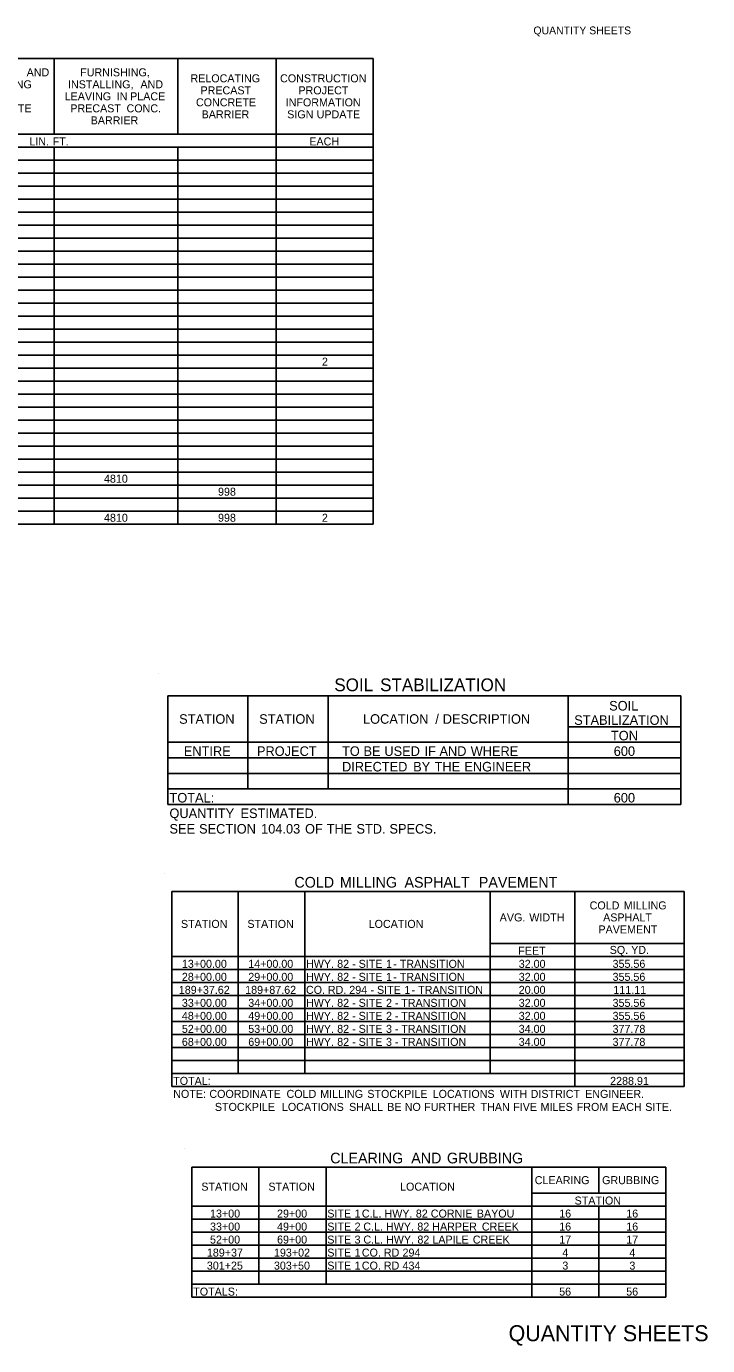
# Model space of a CAD drawing. Extents: x 977434 to 989596, y 1525697 to 1528336.
# Drawn here: x 980105 to 980615, y 1527332 to 1528321 of the extents above; entities that cross this region are included whole.
import ezdxf

# ---------------------------------------------------------------- set-up
doc = ezdxf.new("R2010")
doc.units = 0
for name, color, linetype in [('Default', 7, 'Continuous'), ('R_Border', 7, 'Continuous'), ('R_Border Prem', 7, 'Continuous')]:
    doc.layers.add(name, color=color, linetype=linetype)

msp = doc.modelspace()

# ---------------------------------------------------------------- linework, layer by layer
at = {"layer": 'Default'}
for p, q in [((979105.72, 1528296.72), (980364.94, 1528296.72)), ((980126.06, 1528240.17), (980126.06, 1528296.72)), ((980218.69, 1528240.17), (980218.69, 1528296.72)), ((980292.3, 1527947.67), (980292.3, 1528296.72)), ((980364.94, 1527947.67), (980364.94, 1528296.72)), ((980364.94, 1527947.67), (980364.94, 1528296.72)), ((979749.22, 1528240.17), (980364.94, 1528240.17)), ((980000.29, 1528240.17), (980364.94, 1528240.17)), ((979105.72, 1528230.42), (980364.94, 1528230.42)), ((979691.21, 1528230.42), (980364.94, 1528230.42)), ((980126.06, 1527947.67), (980126.06, 1528230.42)), ((980126.06, 1527947.67), (980126.06, 1528230.42)), ((980218.69, 1527947.67), (980218.69, 1528230.42)), ((980218.69, 1527947.67), (980218.69, 1528230.42)), ((979105.72, 1528220.67), (980364.94, 1528220.67)), ((979105.72, 1528210.92), (980364.94, 1528210.92)), ((979105.72, 1528201.17), (980364.94, 1528201.17)), ((979105.72, 1528191.42), (980364.94, 1528191.42)), ((979105.72, 1528181.67), (980364.94, 1528181.67)), ((979105.72, 1528171.92), (980364.94, 1528171.92)), ((979105.72, 1528162.17), (980364.94, 1528162.17)), ((979105.72, 1528152.42), (980364.94, 1528152.42)), ((979105.72, 1528142.67), (980364.94, 1528142.67)), ((979105.72, 1528132.92), (980364.94, 1528132.92)), ((979105.72, 1528123.17), (980364.94, 1528123.17)), ((979105.72, 1528113.42), (980364.94, 1528113.42)), ((979105.72, 1528103.67), (980364.94, 1528103.67)), ((979105.72, 1528093.92), (980364.94, 1528093.92)), ((979105.72, 1528084.17), (980364.94, 1528084.17)), ((979105.72, 1528074.42), (980364.94, 1528074.42)), ((979105.72, 1528064.67), (980364.94, 1528064.67)), ((979105.72, 1528054.92), (980364.94, 1528054.92)), ((979105.72, 1528045.17), (980364.94, 1528045.17)), ((979105.72, 1528035.42), (980364.94, 1528035.42)), ((979105.72, 1528025.67), (980364.94, 1528025.67)), ((979105.72, 1528015.92), (980364.94, 1528015.92)), ((979105.72, 1528006.17), (980364.94, 1528006.17)), ((979105.72, 1527996.42), (980364.94, 1527996.42)), ((979105.72, 1527986.67), (980364.94, 1527986.67)), ((980048.55, 1527986.67), (980292.3, 1527986.67)), ((980292.3, 1527986.67), (980364.94, 1527986.67)), ((979105.72, 1527976.92), (980364.94, 1527976.92)), ((980048.55, 1527976.92), (980292.3, 1527976.92)), ((980292.3, 1527976.92), (980364.94, 1527976.92)), ((979105.72, 1527967.17), (980364.94, 1527967.17)), ((979105.72, 1527957.42), (980364.94, 1527957.42)), ((979105.72, 1527947.67), (980364.94, 1527947.67)), ((980211.16, 1527819.14), (980595.38, 1527819.14)), ((980211.16, 1527737.63), (980211.16, 1527819.14)), ((980211.16, 1527737.63), (980211.16, 1527819.14)), ((980271.12, 1527749.28), (980271.12, 1527819.14)), ((980331.08, 1527749.28), (980331.08, 1527819.14)), ((980510.97, 1527737.63), (980510.97, 1527819.14)), ((980595.38, 1527737.63), (980595.38, 1527819.14)), ((980595.38, 1527737.63), (980595.38, 1527819.14)), ((980510.97, 1527795.85), (980595.38, 1527795.85)), ((980211.16, 1527784.21), (980595.38, 1527784.21)), ((980211.16, 1527784.21), (980595.38, 1527784.21)), ((980271.12, 1527749.28), (980271.12, 1527784.21)), ((980331.08, 1527749.28), (980331.08, 1527784.21)), ((980510.97, 1527749.28), (980510.97, 1527784.21)), ((980211.16, 1527772.56), (980595.38, 1527772.56)), ((980211.16, 1527760.92), (980595.38, 1527760.92)), ((980211.16, 1527749.28), (980271.12, 1527749.28)), ((980211.16, 1527749.28), (980595.38, 1527749.28)), ((980211.16, 1527737.63), (980595.38, 1527737.63)), ((980214.14, 1527672.44), (980597.8, 1527672.44)), ((980214.14, 1527526.19), (980214.14, 1527672.44)), ((980214.14, 1527526.19), (980214.14, 1527672.44)), ((980263.87, 1527535.94), (980263.87, 1527672.44)), ((980313.59, 1527535.94), (980313.59, 1527672.44)), ((980452.53, 1527535.94), (980452.53, 1527672.44)), ((980515.9, 1527526.19), (980515.9, 1527672.44)), ((980597.8, 1527526.19), (980597.8, 1527672.44)), ((980597.8, 1527526.19), (980597.8, 1527672.44)), ((980452.53, 1527633.44), (980597.8, 1527633.44)), ((980452.53, 1527535.94), (980452.53, 1527633.44)), ((980214.14, 1527623.69), (980597.8, 1527623.69)), ((980263.87, 1527535.94), (980263.87, 1527623.69)), ((980313.59, 1527535.94), (980313.59, 1527623.69)), ((980515.9, 1527535.94), (980515.9, 1527623.69)), ((980214.14, 1527613.94), (980597.8, 1527613.94)), ((980214.14, 1527604.19), (980597.8, 1527604.19)), ((980214.14, 1527594.44), (980597.8, 1527594.44)), ((980214.14, 1527584.69), (980597.8, 1527584.69)), ((980214.14, 1527574.94), (980597.8, 1527574.94)), ((980214.14, 1527565.19), (980597.8, 1527565.19)), ((980214.14, 1527555.44), (980597.8, 1527555.44)), ((980214.14, 1527545.69), (980597.8, 1527545.69)), ((980214.14, 1527535.94), (980263.87, 1527535.94)), ((980214.14, 1527535.94), (980597.8, 1527535.94)), ((980263.87, 1527535.94), (980313.59, 1527535.94)), ((980313.59, 1527535.94), (980452.53, 1527535.94)), ((980515.9, 1527535.94), (980597.8, 1527535.94)), ((980214.14, 1527526.19), (980597.8, 1527526.19)), ((980229.15, 1527465.73), (980584.05, 1527465.73)), ((980229.15, 1527368.23), (980229.15, 1527465.73)), ((980229.15, 1527368.23), (980229.15, 1527465.73)), ((980279.36, 1527377.98), (980279.36, 1527465.73)), ((980329.58, 1527377.98), (980329.58, 1527465.73)), ((980483.63, 1527368.23), (980483.63, 1527465.73)), ((980533.84, 1527446.23), (980533.84, 1527465.73)), ((980584.05, 1527368.23), (980584.05, 1527465.73)), ((980584.05, 1527446.23), (980584.05, 1527465.73)), ((980483.63, 1527446.23), (980584.05, 1527446.23)), ((980483.63, 1527377.98), (980483.63, 1527446.23)), ((980229.15, 1527436.48), (980584.05, 1527436.48)), ((980533.84, 1527368.23), (980533.84, 1527436.48)), ((980533.84, 1527368.23), (980533.84, 1527436.48)), ((980584.05, 1527377.98), (980584.05, 1527436.48)), ((980229.15, 1527426.73), (980584.05, 1527426.73)), ((980229.15, 1527416.98), (980584.05, 1527416.98)), ((980229.15, 1527407.23), (980584.05, 1527407.23)), ((980279.36, 1527377.98), (980279.36, 1527407.23)), ((980329.58, 1527377.98), (980329.58, 1527407.23)), ((980229.15, 1527397.48), (980584.05, 1527397.48)), ((980229.15, 1527387.73), (980584.05, 1527387.73)), ((980229.15, 1527377.98), (980584.05, 1527377.98)), ((980329.58, 1527377.98), (980584.05, 1527377.98)), ((980229.15, 1527368.23), (980584.05, 1527368.23))]:
    msp.add_line(p, q, dxfattribs=at)
at = {"layer": 'R_Border Prem'}
for p, q in [((980204.17, 1527835.44), (980204.17, 1527835.44)), ((980208.29, 1527686.09), (980208.29, 1527686.09)), ((980223.3, 1527479.38), (980223.3, 1527479.38))]:
    msp.add_line(p, q, dxfattribs=at)

# ---------------------------------------------------------------- texts
at = {"layer": 'Default'}
for s, height, p in [(' AND', 6, (980103.1, 1528283.44)), ('FURNISHING,', 6, (980145.43, 1528283.44)), ('INSTALLING', 6, (980062.41, 1528274.44)), ('INSTALLING,', 6, (980136.32, 1528274.44)), (' AND', 6, (980188.35, 1528274.44)), ('RELOCATING', 6, (980228.03, 1528278.94)), ('CONSTRUCTION', 6, (980295.18, 1528278.94)), ('LEAVING', 6, (980133.81, 1528265.44)), (' IN', 6, (980170.57, 1528265.44)), (' PLACE', 6, (980180.61, 1528265.44)), ('PRECAST', 6, (980235.55, 1528269.94)), ('PROJECT', 6, (980308.9, 1528269.94)), ('CONCRETE', 6, (980063.99, 1528256.44)), ('PRECAST', 6, (980138.04, 1528256.44)), (' CONC.', 6, (980177.94, 1528256.44)), ('CONCRETE', 6, (980232.18, 1528260.94)), ('INFORMATION', 6, (980299.38, 1528260.94)), ('BARRIER', 6, (980153.3, 1528247.44)), ('BARRIER', 6, (980236.41, 1528251.94)), ('SIGN', 6, (980300.51, 1528251.94)), (' UPDATE', 6, (980320.34, 1528251.94)), ('LIN.', 6, (980107.37, 1528231.62)), (' FT.', 6, (980122.63, 1528231.62)), ('EACH', 6, (980317.06, 1528231.62)), ('2', 6, (980326.51, 1528066.54)), ('4810', 6, (980163.25, 1527978.79)), ('998', 6, (980248.69, 1527969.04)), ('4810', 6, (980163.26, 1527949.54)), ('998', 6, (980248.69, 1527949.54)), ('2', 6, (980326.5, 1527949.54)), ('SOIL', 9.553, (980335.78, 1527822.51)), (' STABILIZATION', 9.5534, (980366.53, 1527822.51)), ('SOIL', 7.165, (980541.65, 1527808.03)), ('STATION', 7.165, (980219.57, 1527798.09)), ('STATION', 7.165, (980279.53, 1527798.09)), ('LOCATION', 7.165, (980357.3, 1527798.09)), (' /', 7.165, (980408.78, 1527798.09)), (' DESCRIPTION', 7.165, (980414.35, 1527798.09)), ('STABILIZATION', 7.165, (980515.48, 1527797.28)), ('TON', 7.165, (980543.01, 1527785.64)), ('ENTIRE', 7.165, (980223.05, 1527774)), ('PROJECT', 7.165, (980277.84, 1527774)), ('TO', 7.165, (980341.56, 1527774)), (' BE', 7.165, (980355.02, 1527774)), (' USED', 7.165, (980370.62, 1527774)), (' IF', 7.165, (980400.68, 1527774)), (' AND', 7.165, (980411.9, 1527774)), (' WHERE', 7.165, (980435.29, 1527774)), ('600', 7.165, (980545.07, 1527774)), ('DIRECTED', 7.165, (980341.56, 1527762.35)), (' BY', 7.165, (980392.2, 1527762.35)), (' THE', 7.165, (980408.26, 1527762.35)), (' ENGINEER', 7.165, (980430.53, 1527762.35)), ('TOTAL:', 7.165, (980212.32, 1527739.07)), ('600', 7.165, (980545.07, 1527739.07)), ('QUANTITY', 7.165, (980212.32, 1527727.42)), (' ESTIMATED.', 7.165, (980262.86, 1527727.42)), ('SEE', 7.165, (980212.32, 1527715.78)), (' SECTION', 7.165, (980231.82, 1527715.78)), (' 104.03', 7.165, (980278.29, 1527715.78)), (' OF', 7.165, (980311.22, 1527715.78)), (' THE', 7.165, (980327.44, 1527715.78)), (' STD.', 7.165, (980349.71, 1527715.78)), (' SPECS.', 7.165, (980374.43, 1527715.78)), ('COLD', 8, (980305.9, 1527675.27)), (' MILLING', 8, (980337.02, 1527675.27)), (' ASPHALT', 8, (980385.39, 1527675.27)), (' PAVEMENT', 8, (980441.06, 1527675.27)), ('COLD', 6, (980527.05, 1527658.94)), (' MILLING', 6, (980550.38, 1527658.94)), ('STATION', 6, (980220.94, 1527645.07)), ('STATION', 6, (980270.67, 1527645.07)), ('LOCATION', 6, (980361.51, 1527645.07)), ('AVG.', 6, (980459.68, 1527649.94)), (' WIDTH', 6, (980479.6, 1527649.94)), ('PAVEMENT', 6, (980533.65, 1527640.94)), ('ASPHALT', 6, (980537.14, 1527649.94)), ('FEET', 6, (980473.59, 1527624.89)), ('SQ.', 6, (980542.06, 1527625.57)), (' YD.', 6, (980555.92, 1527625.57)), ('13+00.00', 6, (980221.61, 1527615.14)), ('14+00.00', 6, (980271.34, 1527615.14)), ('HWY.', 6, (980314.57, 1527615.14)), (' 82', 6, (980335.72, 1527615.14)), (' -', 6, (980346.93, 1527615.14)), (' SITE', 6, (980351.78, 1527615.14)), (' 1', 6, (980372.3, 1527615.14)), (' -', 6, (980377.75, 1527615.14)), (' TRANSITION', 6, (980382.6, 1527615.14)), ('32.00', 6, (980473.93, 1527615.14)), ('355.56', 6, (980544.23, 1527615.14)), ('28+00.00', 6, (980221.61, 1527605.39)), ('29+00.00', 6, (980271.34, 1527605.39)), ('HWY.', 6, (980314.57, 1527605.39)), (' 82', 6, (980335.72, 1527605.39)), (' -', 6, (980346.93, 1527605.39)), (' SITE', 6, (980351.78, 1527605.39)), (' 1', 6, (980372.3, 1527605.39)), (' -', 6, (980377.75, 1527605.39)), (' TRANSITION', 6, (980382.6, 1527605.39)), ('32.00', 6, (980473.93, 1527605.39)), ('355.56', 6, (980544.23, 1527605.39)), ('189+37.62', 6, (980219.31, 1527595.64)), ('189+87.62', 6, (980269.03, 1527595.64)), ('CO.', 6, (980314.57, 1527595.64)), (' RD.', 6, (980328.74, 1527595.64)), (' 294', 6, (980344.77, 1527595.64)), (' -', 6, (980360.67, 1527595.64)), (' SITE', 6, (980365.53, 1527595.64)), (' 1', 6, (980386.05, 1527595.64)), (' -', 6, (980391.49, 1527595.64)), (' TRANSITION', 6, (980396.35, 1527595.64)), ('20.00', 6, (980473.93, 1527595.64)), ('111.11', 6, (980544.81, 1527595.64)), ('33+00.00', 6, (980221.61, 1527585.89)), ('34+00.00', 6, (980271.34, 1527585.89)), ('HWY.', 6, (980314.57, 1527585.89)), (' 82', 6, (980335.72, 1527585.89)), (' -', 6, (980346.93, 1527585.89)), (' SITE', 6, (980351.78, 1527585.89)), (' 2', 6, (980372.3, 1527585.89)), (' -', 6, (980378.84, 1527585.89)), (' TRANSITION', 6, (980383.7, 1527585.89)), ('32.00', 6, (980473.93, 1527585.89)), ('355.56', 6, (980544.23, 1527585.89)), ('48+00.00', 6, (980221.61, 1527576.14)), ('49+00.00', 6, (980271.34, 1527576.14)), ('HWY.', 6, (980314.57, 1527576.14)), (' 82', 6, (980335.72, 1527576.14)), (' -', 6, (980346.93, 1527576.14)), (' SITE', 6, (980351.78, 1527576.14)), (' 2', 6, (980372.3, 1527576.14)), (' -', 6, (980378.84, 1527576.14)), (' TRANSITION', 6, (980383.7, 1527576.14)), ('32.00', 6, (980473.93, 1527576.14)), ('355.56', 6, (980544.23, 1527576.14)), ('52+00.00', 6, (980221.61, 1527566.39)), ('53+00.00', 6, (980271.34, 1527566.39)), ('HWY.', 6, (980314.57, 1527566.39)), (' 82', 6, (980335.72, 1527566.39)), (' -', 6, (980346.93, 1527566.39)), (' SITE', 6, (980351.78, 1527566.39)), (' 3', 6, (980372.3, 1527566.39)), (' -', 6, (980378.91, 1527566.39)), (' TRANSITION', 6, (980383.76, 1527566.39)), ('34.00', 6, (980473.93, 1527566.39)), ('377.78', 6, (980544.23, 1527566.39)), ('68+00.00', 6, (980221.61, 1527556.64)), ('69+00.00', 6, (980271.34, 1527556.64)), ('HWY.', 6, (980314.57, 1527556.64)), (' 82', 6, (980335.72, 1527556.64)), (' -', 6, (980346.93, 1527556.64)), (' SITE', 6, (980351.78, 1527556.64)), (' 3', 6, (980372.3, 1527556.64)), (' -', 6, (980378.91, 1527556.64)), (' TRANSITION', 6, (980383.76, 1527556.64)), ('34.00', 6, (980473.93, 1527556.64)), ('377.78', 6, (980544.23, 1527556.64)), ('TOTAL:', 6, (980215.12, 1527527.39)), ('2288.91', 6, (980542.39, 1527527.39)), ('NOTE:', 6, (980215.12, 1527517.64)), (' COORDINATE', 6, (980240, 1527517.64)), (' COLD', 6, (980297.78, 1527517.64)), (' MILLING', 6, (980322.95, 1527517.64)), (' STOCKPILE', 6, (980358.29, 1527517.64)), (' LOCATIONS', 6, (980407.23, 1527517.64)), (' WITH', 6, (980457.56, 1527517.64)), (' DISTRICT', 6, (980480.63, 1527517.64)), (' ENGINEER.', 6, (980521.45, 1527517.64)), ('              STOCKPILE', 6, (980215.12, 1527507.89)), (' LOCATIONS', 6, (980294.31, 1527507.89)), (' SHALL', 6, (980344.65, 1527507.89)), (' BE', 6, (980373.24, 1527507.89)), (' NO', 6, (980386.31, 1527507.89)), (' FURTHER', 6, (980400.84, 1527507.89)), (' THAN', 6, (980443.11, 1527507.89)), (' FIVE', 6, (980467.57, 1527507.89)), (' MILES', 6, (980488.09, 1527507.89)), (' FROM', 6, (980515.14, 1527507.89)), (' EACH', 6, (980541.51, 1527507.89)), (' SITE.', 6, (980566.46, 1527507.89)), ('CLEARING', 8, (980332.72, 1527468.56)), (' AND', 8, (980390.42, 1527468.56)), (' GRUBBING', 8, (980417.19, 1527468.56)), ('CLEARING', 6, (980485.93, 1527452.98)), ('GRUBBING', 6, (980536.38, 1527452.98)), ('STATION', 6, (980236.19, 1527448.11)), ('STATION', 6, (980286.41, 1527448.11)), ('LOCATION', 6, (980385.05, 1527448.11)), ('STATION', 6, (980515.78, 1527437.68)), ('13+00', 6, (980242.69, 1527427.93)), ('29+00', 6, (980292.9, 1527427.93)), ('SITE', 6, (980330.55, 1527427.93)), (' 1', 6, (980348.74, 1527427.93)), (' C.L.', 6, (980354.18, 1527427.93)), (' HWY.', 6, (980371.15, 1527427.93)), (' 82', 6, (980394.63, 1527427.93)), (' CORNIE', 6, (980405.84, 1527427.93)), (' BAYOU', 6, (980440.32, 1527427.93)), ('16', 6, (980504.26, 1527427.93)), ('16', 6, (980554.47, 1527427.93)), ('33+00', 6, (980242.69, 1527418.18)), ('49+00', 6, (980292.9, 1527418.18)), ('SITE', 6, (980330.55, 1527418.18)), (' 2', 6, (980348.74, 1527418.18)), (' C.L.', 6, (980355.28, 1527418.18)), (' HWY.', 6, (980372.25, 1527418.18)), (' 82', 6, (980395.73, 1527418.18)), (' HARPER', 6, (980406.94, 1527418.18)), (' CREEK', 6, (980444.09, 1527418.18)), ('16', 6, (980504.26, 1527418.18)), ('16', 6, (980554.47, 1527418.18)), ('52+00', 6, (980242.69, 1527408.43)), ('69+00', 6, (980292.9, 1527408.43)), ('SITE', 6, (980330.55, 1527408.43)), (' 3', 6, (980348.74, 1527408.43)), (' C.L.', 6, (980355.35, 1527408.43)), (' HWY.', 6, (980372.31, 1527408.43)), (' 82', 6, (980395.8, 1527408.43)), (' LAPILE', 6, (980407, 1527408.43)), (' CREEK', 6, (980437.31, 1527408.43)), ('17', 6, (980504.26, 1527408.43)), ('17', 6, (980554.47, 1527408.43)), ('189+37', 6, (980240.35, 1527398.68)), ('193+02', 6, (980290.59, 1527398.68)), ('SITE', 6, (980330.55, 1527398.68)), (' 1', 6, (980348.74, 1527398.68)), (' CO.', 6, (980354.18, 1527398.68)), (' RD', 6, (980370.68, 1527398.68)), (' 294', 6, (980384.67, 1527398.68)), ('4', 6, (980506.61, 1527398.68)), ('4', 6, (980556.82, 1527398.68)), ('301+25', 6, (980240.33, 1527388.93)), ('303+50', 6, (980290.57, 1527388.93)), ('SITE', 6, (980330.55, 1527388.93)), (' 1', 6, (980348.74, 1527388.93)), (' CO.', 6, (980354.18, 1527388.93)), (' RD', 6, (980370.68, 1527388.93)), (' 434', 6, (980384.67, 1527388.93)), ('3', 6, (980506.59, 1527388.93)), ('3', 6, (980556.8, 1527388.93)), ('TOTALS:', 6, (980230.13, 1527369.43)), ('56', 6, (980504.22, 1527369.43)), ('56', 6, (980554.43, 1527369.43))]:
    msp.add_text(s, height=height, dxfattribs=at).set_placement(p)
at = {"layer": 'R_Border'}
msp.add_text('QUANTITY SHEETS', height=12, rotation=360, dxfattribs=at).set_placement((980466.34, 1527335.24))
at = {"layer": 'R_Border Prem'}
msp.add_text('QUANTITY SHEETS', height=5.862, rotation=360, dxfattribs=at).set_placement((980484.92, 1528314.92))

doc.saveas('drawing.dxf')
